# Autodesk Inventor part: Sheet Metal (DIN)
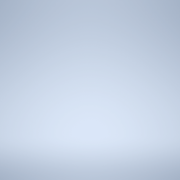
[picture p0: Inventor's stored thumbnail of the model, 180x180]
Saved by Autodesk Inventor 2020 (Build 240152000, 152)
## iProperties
Created: 2019-02
Part Number: Sheet Metal (DIN)
Material: Ogólny
Document SubType Name: Konstrukcja blachowa
Density: 1 g/cm^3
Sheet Metal Rule: Domyślny_mm
Appearance: Domyślna
Catalog Web Link: www.expertbooks.pl
Designer: F.Stasiak
Manager: www.cadconsulting.pl
Company: Fabian Stasiak CAD Consulting
Subject: Zbiór ćwiczeń. Autodesk Inventor 2020. Kurs Professional
Author: F.Stasiak
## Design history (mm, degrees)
other parameters: "Grubość" = 0.5 (derived), "WspółczynnikK" = 4.4, "PromieńGięcia" = 0.5 (= Grubość), "SzerokośćGięciaPodcięcia" = 0.5 (= Grubość), "GłębokośćGięciaPodcięcia" = 0.25 (= 0.5 x Grubość), "RozmiarPodcięciaNarożnika" = 2 (= 4 x Grubość), "OdstępPołączenia" = 0.01, "MinimalnaPozostałość" = 1 (= 2 x Grubość), "PromieńPrzejścia" = 0.5 (= PromieńGięcia), "Rozmiar_promienia_Jacobiego" = 0.5 (= PromieńGięcia), "Wielk_odstępu" = 0.5 (= Grubość)
